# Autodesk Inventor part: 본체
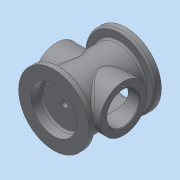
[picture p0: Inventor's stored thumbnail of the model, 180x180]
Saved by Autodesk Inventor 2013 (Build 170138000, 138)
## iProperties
Created: 2018-02
Part Number: 본체
Material: 일반
Document SubType Name: Modeling
Designer: dgall
Density: 1 g/cm^3
Author: dgall
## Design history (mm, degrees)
sketch "스케치1"
  geometry: L1 (0, 0)-(0, 108); L2 (0, 108)-(-52.5, 108); L3 (-52.5, 108)-(-52.5, 98); L4 (-52.5, 98)-(-38, 98); L5 (-38, 98)-(-38, 10); L6 (-38, 10)-(-52.5, 10); L7 (-52.5, 10)-(-52.5, 0); L8 (-52.5, 0)-(0, 0)
  constraints: 16 end point, 4 perpendicular, 3 parallel, 2 equal length, 1 vertical, 1 vertical alignment
  dimensions: "d5" = 108 distance of L1.start L1.end; "d7" = 105 diameter of L3 L1; "d8" = 10 distance of L2.end L3.end; "d9" = 76 diameter of L5 L1
revolve "회전1" sketch "스케치1" stored, may be unused: angle "d10" = 90 deg
node "작업 평면1"
sketch "스케치2"
  geometry: L1 (-108, 52.5)-(-108, -52.5) reference; L2 (-10, 38)-(-98, 38) reference; C1 r 35 at (-54, 0); 3 further points
  constraints: 2 midpoint, 1 centre point, 1 horizontal alignment, 1 vertical alignment
  dimensions: "d12" = 35 radius of C1
extrude "돌출1" join sketch "스케치2" stored distance "d13" = 10; taper "d14" = 0 deg
sketch "스케치3" dims "d15" = 29
  geometry: C1 r 35 at (0, 0) reference; C2 r 24 at (0, 0); 3 further points
  constraints: 2 coincident, 2 horizontal alignment, 1 centre point, 2 other
  dimensions: "d16" = 24 radius of C2
sketch "스케치4"
  geometry: C1 r 52.5 at (0, 0) reference; C2 r 37 at (0, 0)
  constraints: 1 centre point, 1 coincident
  dimensions: "d17" = 37 radius of C2
extrude "돌출2" cut sketch "스케치4" distance "d18" = 7; taper "d19" = 0 deg
sketch "스케치5"
  geometry: C1 r 37 at (0, 0) reference; C2 r 33 at (0, 0)
  constraints: 1 centre point, 1 coincident
  dimensions: "d20" = 33 radius of C2
extrude "돌출3" cut sketch "스케치5" distance "d21" = 79; taper "d22" = 0 deg
sketch "스케치6"
  geometry: C1 r 52.5 at (0, 0) reference; C2 r 34 at (0, 0)
  constraints: 1 centre point, 1 coincident
  dimensions: "d23" = 34 radius of C2
extrude "돌출4" cut sketch "스케치6" distance "d24" = 16; taper "d25" = 0 deg
sketch "스케치7"
  geometry: C1 r 34 at (0, 0) reference; C2 r 5 at (0, 0)
  constraints: 1 centre point, 1 coincident
  dimensions: "d26" = 5 radius of C2
extrude "돌출5" cut sketch "스케치7" stored distance "d27" = 16; taper "d28" = 0 deg
extrude "돌출6" cut sketch "스케치3" stored distance "d29" = 16; taper "d30" = 0 deg
hole "구멍1" sketch "스케치3" diameter "d31" = 3.242; stored, may be unused: countersink angle "d35" = 90 deg, drill point angle "d37" = 118 deg; dims "d32" = 4, "d33" = 4, "d34" = 2, "d36" = 6
chamfer "모따기1" distance "d41" = 1; stored, may be unused: second distance "d42" = 2, angle "d43" = 45 deg
fillet "모깎기1" dims "d44" = 3
fillet "모깎기2" dims "d45" = 3
chamfer "모따기2" distance "d46" = 1; stored, may be unused: second distance "d47" = 2, angle "d48" = 45 deg
chamfer "모따기3" distance "d49" = 1; stored, may be unused: second distance "d50" = 2, angle "d51" = 45 deg
sketch "스케치8" dims "d52" = 45
  geometry: C1 r 52.5 at (0, 0) reference; C2 r 38 at (0, 0) reference; 2 further points
  constraints: 2 vertical alignment, 1 coincident, 2 other
hole "구멍2" sketch "스케치8" at (0, 45) diameter "d53" = 3.242; stored, may be unused: countersink angle "d57" = 90 deg, drill point angle "d59" = 118 deg; dims "d54" = 4, "d55" = 4, "d56" = 2, "d58" = 6
fillet "모깎기3" dims "d63" = 3
fillet "모깎기4" dims "d64" = 3
node "작업 평면2"
sketch "스케치9"
  geometry: L1 (-7, 67)-(-7, 41); L2 (7, 67)-(7, 41); L3 (-50, 89)-(-50, 19) reference; L4 (52.5, 108)-(-52.5, 108) reference; A1 r 7 centre (0, 67) between (7, 67) and (-7, 67); A2 r 7 centre (0, 41) between (-7, 41) and (7, 41); 4 further points
  constraints: 4 end point, 4 point on circle, 3 midpoint, 2 centre point, 2 tangent, 2 vertical alignment, 1 horizontal alignment, 1 parallel
  dimensions: "d66" = 7 radius of A1; "d67" = 7 radius of A2; "d70" = 13 vertical distance of A1.centre point (-7, 54); "d71" = 13 vertical distance of A2.centre point (-7, 54)
extrude "돌출7" join sketch "스케치9" stored distance "d72" = 16; taper "d73" = 15 deg
sketch "스케치10"
  geometry: A1 r 7 centre (0, 67) between (7, 67) and (-7, 67) reference; A2 r 7 centre (0, 41) between (-7, 41) and (7, 41) reference; 3 further points
  constraints: 2 coincident
hole "구멍3" sketch "스케치10" at (0, 67), (0, 41) diameter "d74" = 4.134; stored, may be unused: countersink angle "d78" = 90 deg, drill point angle "d80" = 118 deg; dims "d75" = 6, "d76" = 4, "d77" = 2, "d79" = 8
fillet "모깎기5" dims "d81" = 3
sketch "스케치11"
  geometry: C1 r 49.5 at (0, 0) reference; 1 further point
  constraints: 1 vertical alignment, 1 other
  dimensions: "d82" = 45 distance of point (0, 45) C1.centre
feature "엠보싱1" sketch "스케치11" dims "d5" = 108, "d7" = 105, "d8" = 10, "d9" = 76, "d84" = 0.5, "d85" = 0
node "솔리드1"
pattern_circular "원형 패턴1" dims angle "d39" = 360 deg
mirror "대칭1"
pattern_circular "원형 패턴2" dims angle "d61" = 360 deg
other parameters: "d65" = -55
